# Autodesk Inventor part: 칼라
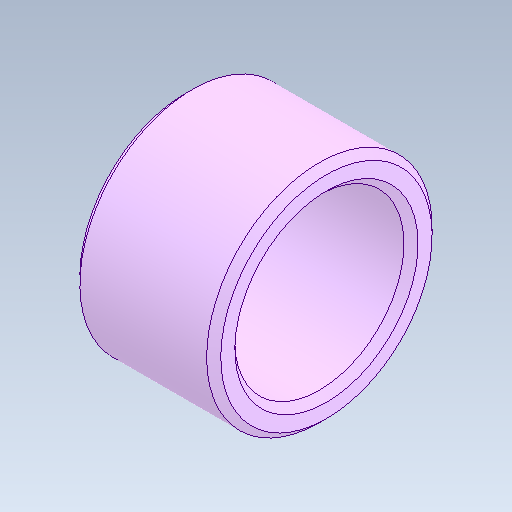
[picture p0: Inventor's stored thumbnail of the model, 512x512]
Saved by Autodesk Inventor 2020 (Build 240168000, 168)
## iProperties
Created: 2024-07
Part Number: 칼라
Material: 강철, 합금
Document SubType Name: Modeling
Designer: oem
Density: 7.73 g/cm^3
Appearance: 기본값
Mass: 6.62967 g
Surface Area: 10.0405 cm^2
Volume: 0.857655 cm^3
Sending System: Autodesk Inventor 2025
Preprocessor: ST-DEVELOPER v20
Author: jhkim
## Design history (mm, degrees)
feature "솔리드1"
node "솔리드2"
